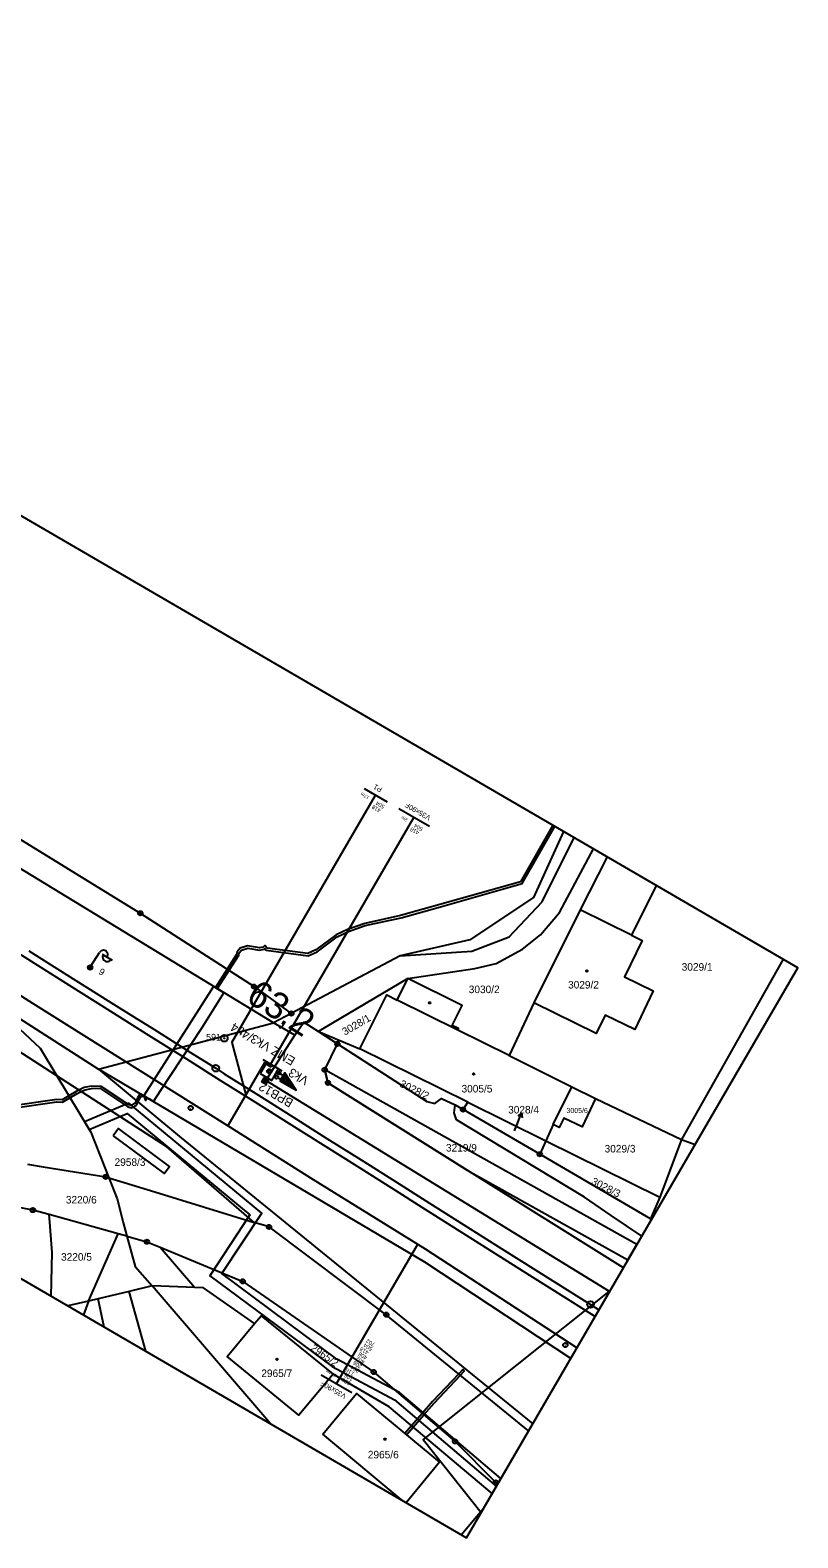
# Model space of a CAD drawing. Extents: x -620765 to -620328, y -1122680 to -1122340.
# Drawn here: x -620500.6 to -620327.7, y -1122679.9 to -1122340.4 of the extents above; entities that cross this region are included whole.
import ezdxf

# ---------------------------------------------------------------- set-up
doc = ezdxf.new("R2010")
doc.units = 0
for name, color, linetype in [('HranDP', 7, 'Continuous'), ('Hranice parcel', 7, 'Continuous'), ('Parcelní čísla', 7, 'Continuous'), ('Pop  PČ popisy', 7, 'Continuous'), ('Rámečky-tisk', 7, 'Continuous'), ('Vnitřní kresba', 7, 'Continuous'), ('Vrstva 1', 7, 'Continuous'), ('Vrstva 14', 7, 'Continuous'), ('Vrstva 2', 7, 'Continuous'), ('Vrstva 25', 7, 'Continuous'), ('Vrstva 3', 7, 'Continuous'), ('Vrstva 33', 7, 'Continuous'), ('Vrstva 7', 7, 'Continuous'), ('Věcná břemena k části', 7, 'Continuous'), ('Značky bodu BP', 7, 'Continuous'), ('Značky budov', 7, 'Continuous')]:
    doc.layers.add(name, color=color, linetype=linetype)

msp = doc.modelspace()

# ---------------------------------------------------------------- linework, layer by layer
at = {"layer": 'HranDP'}
for p, q in [((-620445.8, -1122563.95), (-620552.09, -1122499.2)), ((-620511.29, -1122557.64), (-620485.21, -1122574.33)), ((-620440.98, -1122566.69), (-620445.8, -1122563.95)), ((-620435.69, -1122565.88), (-620431.39, -1122568.66))]:
    msp.add_line(p, q, dxfattribs=at)
for points in [[(-620440.98, -1122566.69), (-620438.97, -1122563.76), (-620435.69, -1122565.88)], [(-620366.94, -1122619.06), (-620402.13, -1122597.06), (-620433.53, -1122577.42), (-620434.26, -1122574.5), (-620431.39, -1122568.66)], [(-620378.83, -1122639.51), (-620411.71, -1122617.81), (-620485.21, -1122574.33)]]:
    msp.add_lwpolyline(points, dxfattribs=at)
at = {"layer": 'Hranice parcel'}
for p, q in [((-620548.9, -1122494.24), (-620475.79, -1122539.24)), ((-620445.8, -1122563.95), (-620552.09, -1122499.2)), ((-620370.65, -1122526.52), (-620376.68, -1122538.44)), ((-620376.68, -1122538.44), (-620387.17, -1122559.43)), ((-620365.17, -1122544.19), (-620376.68, -1122538.44)), ((-620330.98, -1122549.59), (-620353.86, -1122590.22)), ((-620511.29, -1122557.64), (-620485.21, -1122574.33)), ((-620441.78, -1122561.82), (-620445.8, -1122563.95)), ((-620387.17, -1122559.43), (-620392.72, -1122571.3)), ((-620440.98, -1122566.69), (-620445.8, -1122563.95)), ((-620435.69, -1122565.88), (-620426.32, -1122569.77)), ((-620435.69, -1122565.88), (-620431.39, -1122568.66)), ((-620402.04, -1122581.77), (-620426.32, -1122569.77)), ((-620392.72, -1122571.3), (-620378.57, -1122578.31)), ((-620382.82, -1122586.79), (-620378.57, -1122578.31)), ((-620378.57, -1122578.31), (-620373.23, -1122580.96)), ((-620403.1, -1122583.45), (-620402.04, -1122581.77)), ((-620402.04, -1122581.77), (-620384.45, -1122590.46)), ((-620373.23, -1122580.96), (-620353.86, -1122590.22)), ((-620385.78, -1122593.52), (-620403.1, -1122583.45)), ((-620382.82, -1122586.79), (-620384.45, -1122590.46)), ((-620384.45, -1122590.46), (-620385.78, -1122593.52)), ((-620384.45, -1122590.46), (-620358.78, -1122603.15)), ((-620353.86, -1122590.22), (-620358.78, -1122603.15)), ((-620353.86, -1122590.22), (-620350.82, -1122591.33)), ((-620360.83, -1122608.03), (-620385.78, -1122593.52)), ((-620482.88, -1122598.82), (-620481, -1122603.54)), ((-620358.78, -1122603.15), (-620360.83, -1122608.03)), ((-620446.79, -1122609.88), (-620450.13, -1122608.86)), ((-620360.83, -1122608.03), (-620360.69, -1122608.3)), ((-620478.83, -1122611.96), (-620476.96, -1122618.82)), ((-620476.96, -1122618.82), (-620473.14, -1122623.15)), ((-620473.14, -1122623.15), (-620478.32, -1122624.38)), ((-620478.32, -1122624.38), (-620485.31, -1122626.04))]:
    msp.add_line(p, q, dxfattribs=at)
for points in [[(-620380.48, -1122520.8), (-620387.25, -1122535.69), (-620401.53, -1122545.24), (-620417.25, -1122548.82), (-620441.78, -1122561.82)], [(-620359.58, -1122532.96), (-620365.17, -1122544.19)], [(-620475.79, -1122539.24), (-620450.17, -1122555.76), (-620441.78, -1122561.82)], [(-620365.17, -1122544.19), (-620362.75, -1122545.4), (-620366.73, -1122553.56), (-620360.24, -1122556.72), (-620364.41, -1122565.4), (-620371.05, -1122562.22), (-620373.07, -1122566.34), (-620387.17, -1122559.43)], [(-620415.52, -1122553.94), (-620434.68, -1122565.28), (-620435.69, -1122565.88)], [(-620426.32, -1122569.77), (-620420.27, -1122557.63), (-620417.91, -1122558.83), (-620415.52, -1122553.94)], [(-620392.72, -1122571.3), (-620404.28, -1122565.56), (-620404.12, -1122565.22), (-620405.52, -1122564.49), (-620403.26, -1122560.03), (-620415.52, -1122553.94)], [(-620511.29, -1122557.64), (-620498.35, -1122569.65), (-620494.61, -1122575.85)], [(-620440.98, -1122566.69), (-620438.97, -1122563.76), (-620435.69, -1122565.88)], [(-620370.06, -1122624.43), (-620447.48, -1122576.88), (-620440.98, -1122566.69)], [(-620366.94, -1122619.06), (-620402.13, -1122597.06), (-620433.53, -1122577.42), (-620434.26, -1122574.5), (-620431.39, -1122568.66)], [(-620431.39, -1122568.66), (-620411.27, -1122581.65), (-620409.46, -1122582.07), (-620407.91, -1122580.98), (-620404.87, -1122582.42), (-620403.1, -1122583.45)], [(-620494.61, -1122575.85), (-620486.95, -1122588.56), (-620482.88, -1122598.82)], [(-620450.13, -1122608.86), (-620469.8, -1122591.86), (-620494.61, -1122575.85)], [(-620485.21, -1122574.33), (-620466.94, -1122589.51), (-620387.37, -1122654.2)], [(-620378.83, -1122639.51), (-620411.71, -1122617.81), (-620485.21, -1122574.33)], [(-620373.23, -1122580.96), (-620376.29, -1122587.36), (-620380.38, -1122585.36), (-620381.45, -1122587.52), (-620382.82, -1122586.79)], [(-620501.2, -1122595.75), (-620497.68, -1122596.32), (-620483.58, -1122598.6), (-620482.88, -1122598.82)], [(-620482.88, -1122598.82), (-620472.56, -1122601.98), (-620450.13, -1122608.86)], [(-620496.31, -1122607.11), (-620500, -1122606.09), (-620502.69, -1122605.61)], [(-620481, -1122603.54), (-620479.67, -1122608.86), (-620478.83, -1122611.96)], [(-620495.89, -1122625.48), (-620495.65, -1122615.65), (-620496.18, -1122608.79), (-620496.31, -1122607.11)], [(-620478.83, -1122611.96), (-620480.79, -1122611.41), (-620496.31, -1122607.11)], [(-620388.31, -1122655.82), (-620420.38, -1122629.64), (-620446.79, -1122609.88)], [(-620478.83, -1122611.96), (-620474.31, -1122613.21), (-620471.33, -1122614.44), (-620452.73, -1122622.13)], [(-620450.04, -1122631.61), (-620461.53, -1122623.57), (-620463.51, -1122623.5), (-620473.14, -1122623.15)], [(-620446.38, -1122654.27), (-620473.14, -1122623.15)], [(-620452.73, -1122622.13), (-620423.22, -1122642.55), (-620404.9, -1122658.18), (-620395.68, -1122667.41), (-620395.25, -1122667.75)], [(-620485.31, -1122626.04), (-620487.46, -1122626.56), (-620492.12, -1122627.67)], [(-620483.94, -1122632.42), (-620485.31, -1122626.04)], [(-620474.55, -1122637.88), (-620478.32, -1122624.38)], [(-620450.04, -1122631.61), (-620448.58, -1122629.86), (-620432.38, -1122643.03)], [(-620432.38, -1122643.03), (-620440.08, -1122652.3), (-620456.23, -1122639.05), (-620450.04, -1122631.61)], [(-620396.5, -1122669.89), (-620419.73, -1122650.41), (-620432.38, -1122643.03)], [(-620434.7, -1122656.53), (-620427.07, -1122647.39), (-620408.37, -1122662.86), (-620415.93, -1122671.97)], [(-620416.56, -1122671.6), (-620434.7, -1122656.53)], [(-620403.48, -1122679.21), (-620398.37, -1122673.11)]]:
    msp.add_lwpolyline(points, dxfattribs=at)
at = {"layer": 'Pop  PČ popisy'}
for p, q in [((-620390.98, -1122586.98), (-620389.91, -1122584.18)), ((-620389.91, -1122584.18), (-620390.73, -1122584.93)), ((-620389.91, -1122584.18), (-620389.8, -1122585.29)), ((-620391.48, -1122588.26), (-620390.98, -1122586.98))]:
    msp.add_line(p, q, dxfattribs=at)
at = {"layer": 'Rámečky-tisk'}
msp.add_line((-620399.01, -1122674.21), (-620369.88, -1122624.12), dxfattribs=at)
for points in [[(-620690.75, -1122340.39), (-620765.39, -1122468.77), (-620402.31, -1122679.89)], [(-620402.31, -1122679.89), (-620327.66, -1122551.51), (-620690.75, -1122340.39)], [(-620369.88, -1122624.12), (-620412.11, -1122657.76), (-620399.01, -1122674.21)]]:
    msp.add_lwpolyline(points, dxfattribs=at)
at = {"layer": 'Vnitřní kresba'}
for p, q in [((-620385.3, -1122536.65), (-620378.09, -1122522.19)), ((-620381.37, -1122539.08), (-620373.72, -1122524.73)), ((-620392.7, -1122544.53), (-620385.3, -1122536.65)), ((-620385.63, -1122544.07), (-620381.37, -1122539.08)), ((-620401.09, -1122547.76), (-620392.7, -1122544.53)), ((-620389.68, -1122547.33), (-620385.63, -1122544.07)), ((-620417.25, -1122548.82), (-620401.09, -1122547.76)), ((-620395.61, -1122550.55), (-620389.68, -1122547.33)), ((-620415.52, -1122553.94), (-620400.46, -1122551.66)), ((-620400.46, -1122551.66), (-620395.61, -1122550.55)), ((-620404.28, -1122565.56), (-620417.91, -1122558.83)), ((-620485.21, -1122574.33), (-620445.8, -1122563.95)), ((-620494.61, -1122575.85), (-620503.56, -1122570.07)), ((-620405.1, -1122584.22), (-620404.87, -1122582.42)), ((-620404.53, -1122585.79), (-620405.1, -1122584.22)), ((-620375.73, -1122603.21), (-620404.53, -1122585.79)), ((-620369.73, -1122607.28), (-620375.73, -1122603.21)), ((-620362.82, -1122611.98), (-620369.73, -1122607.28)), ((-620487.46, -1122626.56), (-620480.79, -1122611.41)), ((-620471.33, -1122614.44), (-620463.51, -1122623.5)), ((-620487.46, -1122626.56), (-620488.62, -1122629.7))]:
    msp.add_line(p, q, dxfattribs=at)
at = {"layer": 'Vrstva 1'}
for p, q in [((-620447.82, -1122572.96), (-620456.11, -1122587.12)), ((-620446.31, -1122573.89), (-620447.82, -1122572.96)), ((-620445.97, -1122573.52), (-620446.31, -1122573.89))]:
    msp.add_line(p, q, dxfattribs=at)
for points in [[(-620456.11, -1122587.12), (-620500.01, -1122559.59), (-620522.22, -1122545.45), (-620544.95, -1122530.86)], [(-620500.94, -1122547.69), (-620490.94, -1122553.98), (-620482.44, -1122559.31), (-620477.26, -1122562.56), (-620472.76, -1122565.38), (-620464.48, -1122570.59), (-620458.81, -1122574.16), (-620456.89, -1122575.37), (-620449.16, -1122580.24), (-620441.4, -1122585.12), (-620433.76, -1122589.94), (-620426.06, -1122594.79), (-620418.33, -1122599.67), (-620410.68, -1122604.49), (-620402.92, -1122609.38), (-620394.33, -1122614.78), (-620386.67, -1122619.61), (-620379.01, -1122624.44), (-620374.38, -1122627.36), (-620372.47, -1122628.57)], [(-620447.82, -1122572.96), (-620447.82, -1122572.96), (-620447.82, -1122572.96), (-620447.82, -1122572.96), (-620447.82, -1122572.96)], [(-620377.43, -1122637.1), (-620411.56, -1122614.92), (-620436.76, -1122599.26), (-620456.11, -1122587.12)]]:
    msp.add_lwpolyline(points, dxfattribs=at)
at = {"layer": 'Vrstva 14'}
msp.add_lwpolyline([(-620510.69, -1122543.55), (-620509.04, -1122544.63), (-620501.84, -1122549.15), (-620491.85, -1122555.41), (-620483.32, -1122560.77), (-620478.25, -1122563.97), (-620473.97, -1122566.66), (-620465.4, -1122572.05), (-620457.72, -1122576.88), (-620450.01, -1122581.72), (-620442.29, -1122586.56), (-620434.63, -1122591.38), (-620426.95, -1122596.21), (-620419.24, -1122601.09), (-620411.54, -1122605.96), (-620403.8, -1122610.84), (-620395.25, -1122616.25), (-620387.51, -1122621.12), (-620379.87, -1122625.94), (-620375.57, -1122628.64), (-620373.33, -1122630.05)], dxfattribs=at)
at = {"layer": 'Vrstva 2'}
for p, q in [((-620443.81, -1122574.78), (-620448.14, -1122572.26)), ((-620447.27, -1122572.77), (-620448.78, -1122575.36)), ((-620448.78, -1122575.36), (-620446.19, -1122576.87)), ((-620444.68, -1122574.27), (-620447.27, -1122572.77)), ((-620446.28, -1122574.6), (-620447.22, -1122574.84)), ((-620446.27, -1122575.01), (-620447.03, -1122575.21)), ((-620446.19, -1122576.87), (-620444.68, -1122574.27)), ((-620447.66, -1122576.93), (-620448.38, -1122577.12)), ((-620447.75, -1122577.09), (-620448.38, -1122577.25)), ((-620447.57, -1122576.77), (-620448.28, -1122576.96)), ((-620447.85, -1122577.25), (-620448.22, -1122577.35)), ((-620447.47, -1122576.61), (-620448.19, -1122576.8)), ((-620447.59, -1122576.5), (-620448.1, -1122576.64)), ((-620447.94, -1122577.41), (-620448.06, -1122577.44)), ((-620447.75, -1122576.41), (-620448, -1122576.48))]:
    msp.add_line(p, q, dxfattribs=at)
for points in [[(-620447.98, -1122577.49), (-620448.44, -1122577.22), (-620447.91, -1122576.32), (-620447.46, -1122576.58)], [(-620447.98, -1122577.49), (-620448.44, -1122577.22), (-620447.91, -1122576.32), (-620447.46, -1122576.58)], [(-620447.53, -1122577.75), (-620448.44, -1122577.22), (-620447.91, -1122576.32), (-620447, -1122576.84)]]:
    msp.add_lwpolyline(points, close=True, dxfattribs=at)
msp.add_circle((-620446.73, -1122574.82), 0.5, dxfattribs=at)
at = {"layer": 'Vrstva 25'}
for p, q in [((-620486.83, -1122551.02), (-620484.96, -1122548.06)), ((-620484.37, -1122548.43), (-620482.17, -1122549.81)), ((-620487.57, -1122551.32), (-620486.72, -1122551.12)), ((-620487.53, -1122551.69), (-620486.59, -1122551.48))]:
    msp.add_line(p, q, dxfattribs=at)
msp.add_circle((-620487.09, -1122551.45), 0.5, dxfattribs=at)
for centre, start, end in [((-620484.12, -1122548.59), 327.8803, 147.8803), ((-620483.28, -1122549.13), 147.1777, 328.5829)]:
    msp.add_arc(centre, 1, start, end, dxfattribs=at)
at = {"layer": 'Vrstva 3'}
for p, q in [((-620444.89, -1122575.19), (-620444.27, -1122575.02)), ((-620444.82, -1122575.44), (-620444.2, -1122575.28)), ((-620444.4, -1122575.32), (-620443.63, -1122575.77)), ((-620443.92, -1122576.26), (-620442.75, -1122575.96)), ((-620443.73, -1122575.94), (-620442.9, -1122575.73)), ((-620443.54, -1122575.62), (-620443.06, -1122575.49)), ((-620443.36, -1122575.3), (-620443.21, -1122575.26)), ((-620444.15, -1122576.7), (-620444.75, -1122576.35)), ((-620444.29, -1122576.91), (-620442.45, -1122576.42)), ((-620444.1, -1122576.59), (-620442.6, -1122576.19)), ((-620444.08, -1122577.12), (-620442.3, -1122576.65)), ((-620443.76, -1122577.31), (-620442.15, -1122576.88)), ((-620443.44, -1122577.5), (-620441.99, -1122577.11)), ((-620443.12, -1122577.68), (-620441.84, -1122577.35)), ((-620442.79, -1122577.87), (-620441.69, -1122577.58)), ((-620442.47, -1122578.06), (-620441.54, -1122577.81)), ((-620442.15, -1122578.24), (-620441.39, -1122578.04)), ((-620441.83, -1122578.43), (-620441.23, -1122578.27)), ((-620441.51, -1122578.62), (-620441.08, -1122578.5)), ((-620441.19, -1122578.8), (-620440.93, -1122578.73)), ((-620440.87, -1122578.99), (-620440.78, -1122578.96))]:
    msp.add_line(p, q, dxfattribs=at)
msp.add_lwpolyline([(-620444.33, -1122576.98), (-620440.7, -1122579.09), (-620443.27, -1122575.16)], close=True, dxfattribs=at)
for centre in [(-620445.08, -1122576.15), (-620444.55, -1122575.23)]:
    msp.add_circle(centre, 0.35, dxfattribs=at)
at = {"layer": 'Vrstva 33'}
for p, q in [((-620425.38, -1122511.12), (-620420.19, -1122514.14)), ((-620455.16, -1122568.32), (-620422.78, -1122512.63)), ((-620446.7, -1122573.65), (-620414.14, -1122517.65)), ((-620417.59, -1122515.64), (-620410.68, -1122519.66)), ((-620455.16, -1122568.32), (-620452.03, -1122580.15)), ((-620413.36, -1122613.8), (-620431.59, -1122645.16)), ((-620435.05, -1122643.15), (-620428.14, -1122647.17))]:
    msp.add_line(p, q, dxfattribs=at)
at = {"layer": 'Vrstva 7'}
for p, q in [((-620464.48, -1122583.08), (-620464.39, -1122583.13)), ((-620380.09, -1122636.45), (-620380.01, -1122636.5))]:
    msp.add_line(p, q, dxfattribs=at)
for centre, radius in [((-620458.81, -1122574.16), 0.75), ((-620464.44, -1122583.1), 0.5), ((-620374.38, -1122627.36), 0.75), ((-620380.05, -1122636.48), 0.5)]:
    msp.add_circle(centre, radius, dxfattribs=at)
at = {"layer": 'Věcná břemena k části'}
for p, q in [((-620382.4, -1122519.69), (-620382.84, -1122519.43)), ((-620365.93, -1122617.32), (-620363.92, -1122613.86)), ((-620395.57, -1122668.3), (-620394.55, -1122666.54))]:
    msp.add_line(p, q, dxfattribs=at)
for points in [[(-620382.84, -1122519.43), (-620390.13, -1122532.15), (-620408.3, -1122537.29), (-620417.17, -1122539.78), (-620425.25, -1122541.55), (-620429.09, -1122542.9), (-620431.68, -1122544.11), (-620436.23, -1122547.48), (-620438.03, -1122548.3), (-620447.21, -1122547.08), (-620447.75, -1122546.49), (-620448.13, -1122546.86), (-620448.94, -1122547.05), (-620451.62, -1122546.56), (-620453.33, -1122547.1), (-620454, -1122547.92), (-620454.09, -1122548.53), (-620458.89, -1122555.98), (-620458.46, -1122556.24), (-620453.61, -1122548.71), (-620453.52, -1122548.14), (-620453.03, -1122547.54), (-620451.58, -1122547.08), (-620448.92, -1122547.57), (-620447.89, -1122547.32), (-620447.77, -1122547.21), (-620447.45, -1122547.56), (-620437.95, -1122548.82), (-620435.97, -1122547.92), (-620431.42, -1122544.55), (-620428.91, -1122543.36), (-620425.11, -1122542.03), (-620417.05, -1122540.26), (-620408.16, -1122537.77), (-620389.79, -1122532.57), (-620382.4, -1122519.69)], [(-620363.92, -1122613.86), (-620434.26, -1122574.5), (-620433.53, -1122577.42), (-620402.13, -1122597.06), (-620365.93, -1122617.32)], [(-620394.55, -1122666.54), (-620417.42, -1122647.16), (-620431.52, -1122639.64), (-620457.44, -1122620.38), (-620448.45, -1122606.75), (-620478.4, -1122581.98), (-620488.36, -1122586.21), (-620487.32, -1122587.95), (-620478.74, -1122584.3), (-620451.11, -1122607.15), (-620460.16, -1122620.86), (-620432.6, -1122641.34), (-620418.54, -1122648.82), (-620395.57, -1122668.3)]]:
    msp.add_lwpolyline(points, dxfattribs=at)
for points in [[(-620456.96, -1122557.15), (-620459.28, -1122555.74), (-620474.94, -1122580.24), (-620474.78, -1122580.35), (-620474.85, -1122580.46), (-620473.73, -1122581.12), (-620473.69, -1122581.06), (-620472.83, -1122581.63), (-620471.16, -1122579.11), (-620461.86, -1122564.94)], [(-620476.66, -1122582.45), (-620476.31, -1122581.73), (-620476.7, -1122581.4), (-620477.04, -1122582.09), (-620477.83, -1122582.55), (-620478.41, -1122582.37), (-620484.64, -1122578.24), (-620486.9, -1122578.2), (-620488.41, -1122578.51), (-620489.62, -1122579.07), (-620490.27, -1122579.37), (-620491.9, -1122580.35), (-620491.64, -1122580.78), (-620490.03, -1122579.81), (-620489.12, -1122579.39), (-620488.25, -1122578.99), (-620486.8, -1122578.7), (-620484.92, -1122578.66), (-620478.63, -1122582.83), (-620477.77, -1122583.09)], [(-620505.65, -1122583.07), (-620505.06, -1122583.21), (-620494.61, -1122581.71), (-620493.3, -1122581.78), (-620491.64, -1122580.78), (-620491.9, -1122580.35), (-620493.42, -1122581.28), (-620494.63, -1122581.21), (-620505.04, -1122582.71), (-620506.06, -1122582.46)], [(-620476.7, -1122581.4), (-620476.31, -1122581.73), (-620475.97, -1122581.04), (-620475.6, -1122580.46), (-620475.01, -1122580.41), (-620474.65, -1122581.39), (-620474.27, -1122580.8), (-620474.85, -1122580.46), (-620475.69, -1122579.96), (-620475.88, -1122579.98), (-620476.41, -1122580.8)], [(-620481.88, -1122589.35), (-620470.44, -1122597.88), (-620469.24, -1122596.28), (-620480.68, -1122587.75)], [(-620414.7, -1122654.63), (-620414.31, -1122654.95), (-620411.9, -1122652.2), (-620409.58, -1122649.55), (-620403.69, -1122643.27), (-620402.81, -1122642.33), (-620403.17, -1122641.99), (-620404.07, -1122642.95), (-620409.97, -1122649.21), (-620412.29, -1122651.87)], [(-620415.83, -1122656.69), (-620414.31, -1122654.95), (-620414.7, -1122654.63), (-620416.22, -1122656.37)]]:
    msp.add_lwpolyline(points, close=True, dxfattribs=at)
at = {"layer": 'Značky bodu BP'}
for centre, radius in [((-620475.79, -1122539.24), 0.5), ((-620475.79, -1122539.24), 0.0303), ((-620450.17, -1122555.76), 0.5), ((-620450.17, -1122555.76), 0.0303), ((-620441.78, -1122561.82), 0.5), ((-620441.78, -1122561.82), 0.0303), ((-620456.87, -1122567.4), 0.75), ((-620456.87, -1122567.4), 0.03), ((-620431.39, -1122568.66), 0.5), ((-620431.39, -1122568.66), 0.0303), ((-620434.26, -1122574.5), 0.5), ((-620434.26, -1122574.5), 0.0303), ((-620433.53, -1122577.42), 0.5), ((-620433.53, -1122577.42), 0.0303), ((-620403.1, -1122583.45), 0.5), ((-620403.1, -1122583.45), 0.0303), ((-620385.78, -1122593.52), 0.5), ((-620385.78, -1122593.52), 0.0303), ((-620483.58, -1122598.6), 0.5), ((-620483.58, -1122598.6), 0.0303), ((-620500, -1122606.09), 0.5), ((-620500, -1122606.09), 0.0303), ((-620446.79, -1122609.88), 0.5), ((-620446.79, -1122609.88), 0.0303), ((-620474.31, -1122613.21), 0.5), ((-620474.31, -1122613.21), 0.0303), ((-620452.73, -1122622.13), 0.5), ((-620452.73, -1122622.13), 0.0303), ((-620420.38, -1122629.64), 0.5), ((-620420.38, -1122629.64), 0.0303), ((-620423.22, -1122642.55), 0.5), ((-620423.22, -1122642.55), 0.0303), ((-620404.9, -1122658.18), 0.5), ((-620404.9, -1122658.18), 0.0303), ((-620395.68, -1122667.41), 0.5), ((-620395.68, -1122667.41), 0.0303)]:
    msp.add_circle(centre, radius, dxfattribs=at)
at = {"layer": 'Značky budov'}
for centre in [(-620375.21, -1122552.24), (-620410.6, -1122559.41), (-620400.72, -1122575.42), (-620444.99, -1122639.7), (-620420.66, -1122657.67)]:
    msp.add_circle(centre, 0.175, dxfattribs=at)

# ---------------------------------------------------------------- texts
at = {"layer": 'Parcelní čísla'}
for s, height, p in [('3029/1', 1.7, (-620353.83, -1122552.18)), ('3030/2', 1.7, (-620401.8, -1122557.23)), ('3029/2', 1.7, (-620379.43, -1122556.19)), ('3005/5', 1.7, (-620403.43, -1122579.6)), ('3028/4', 1.7, (-620392.93, -1122584.33)), ('3005/6', 1.139, (-620379.78, -1122584.23)), ('3219/9', 1.7, (-620406.93, -1122592.9)), ('3029/3', 1.7, (-620371.2, -1122593.11)), ('2958/3', 1.7, (-620481.59, -1122596.14)), ('3220/6', 1.7, (-620492.57, -1122604.6)), ('3220/5', 1.7, (-620493.65, -1122617.48)), ('2965/7', 1.7, (-620448.53, -1122643.68)), ('2965/6', 1.7, (-620424.54, -1122662))]:
    msp.add_text(s, height=height, dxfattribs=at).set_placement(p)
for s, rotation, p in [('3028/1', 30, (-620429.73, -1122566.82)), ('3028/2', 334, (-620417.52, -1122578.22)), ('3028/3', 333, (-620374.36, -1122600.16)), ('2965/2', 325, (-620437.6, -1122637.48))]:
    msp.add_text(s, height=1.7, rotation=rotation, dxfattribs=at).set_placement(p)
at = {"layer": 'Vrstva 25'}
msp.add_text('9', height=1.5, rotation=327.8803, dxfattribs=at).set_placement((-620485.33, -1122552.79))
at = {"layer": 'Vrstva 3'}
for s, p in [('EMZ Vk3/4t/4', (-620440.69, -1122571.92)), ('Vk3', (-620437.67, -1122576.33)), ('BPB12', (-620441.14, -1122581.35))]:
    msp.add_text(s, height=2, rotation=149.8236, dxfattribs=at).set_placement(p)
at = {"layer": 'Vrstva 33'}
for s, height, p in [('P1', 1.15, (-620421.17, -1122511.08)), ('17m', 0.75, (-620424.15, -1122512.99)), ('418', 0.9, (-620421.52, -1122515.85)), ('504', 0.9, (-620420.66, -1122515.02)), ('V35x90F', 1.15, (-620410.24, -1122517.43)), ('2m', 0.75, (-620415.5, -1122518.02)), ('418', 0.9, (-620412.87, -1122520.88)), ('504', 0.9, (-620412.02, -1122520.04)), ('418', 0.9, (-620424.25, -1122637.92)), ('504', 0.9, (-620423.39, -1122637.09)), ('702', 0.9, (-620422.84, -1122636.08)), ('206', 0.9, (-620425.77, -1122641.03)), ('402', 0.9, (-620425.13, -1122640.07)), ('408', 0.9, (-620424.55, -1122639.07)), ('154m', 0.75, (-620431.58, -1122643.14)), ('102', 0.9, (-620428.33, -1122644.86)), ('108', 0.9, (-620427.75, -1122643.86)), ('116', 0.9, (-620427.48, -1122642.69)), ('204', 0.9, (-620426.28, -1122642.06)), ('V35x90F', 1.15, (-620429.28, -1122647.66))]:
    msp.add_text(s, height=height, rotation=149.8236, dxfattribs=at).set_placement(p)
at = {"layer": 'Vrstva 7'}
msp.add_text('63,2', height=6, rotation=327.8019, dxfattribs=at).set_placement((-620452.26, -1122558.96))
at = {"layer": 'Značky bodu BP'}
msp.add_text('591', height=1.5, dxfattribs=at).set_placement((-620460.97, -1122567.9))

doc.saveas('drawing.dxf')
